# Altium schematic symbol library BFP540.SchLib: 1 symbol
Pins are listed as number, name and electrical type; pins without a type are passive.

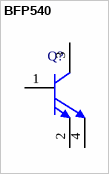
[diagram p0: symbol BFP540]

## BFP540
designator Q?
NPN Silicon RF Transistor, 4.5 V VCEO, 80 mA IC, 21.5 dB Gmax, SOT343, Green; Manufacturer: Infineon; PartNumber: BFP540; Gmax (typ): 21.5 dB; Green: yes; IC (max): 80 mA; NFmin (typ): 0.9 dB; Ptot (max): 250 mW; VCEO (max): 4.5 V
footprint INF-SOT343_V (SOT343, 4-Leads, Body 2x1.25 mm)
pins: 1 B, 2 E, 3 C, 4 E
